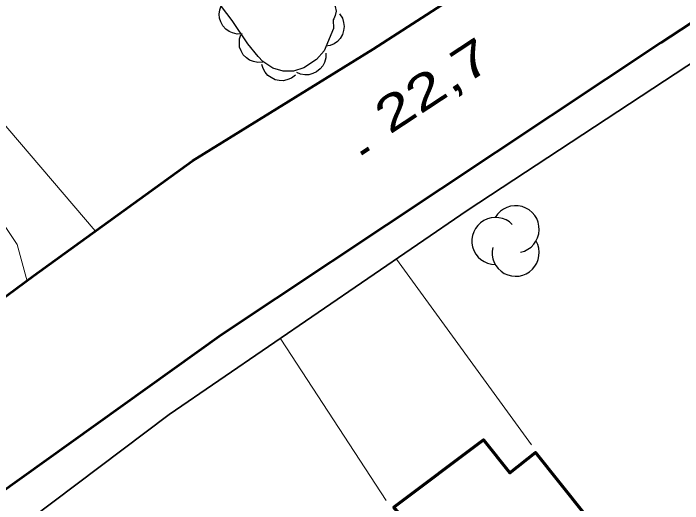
# Model space of a CAD drawing. Extents: x 356765 to 358572, y 5103174 to 5104650.
# Drawn here: x 357410.7 to 357439.35, y 5103860.56 to 5103881.56 of the extents above; entities that cross this region are included whole.
import ezdxf

# ---------------------------------------------------------------- set-up
doc = ezdxf.new("R2010")
doc.units = 0
doc.header["$LTSCALE"] = 0.6
doc.linetypes.add('DOT_DASHED', pattern=[7.7, 5, -1.2, 0.3, -1.2])
for name, color, linetype, lineweight in [('19', 7, 'Continuous', 13), ('21', 7, 'Continuous', 53), ('22', 7, 'Continuous', 35), ('3', 7, 'Continuous', 140), ('31', 7, 'Continuous', 70), ('44', 7, 'Continuous', 25)]:
    doc.layers.add(name, color=color, linetype=linetype, lineweight=lineweight)

msp = doc.modelspace()

# ---------------------------------------------------------------- linework, layer by layer
at = {"layer": '19'}
for p, q in [((357407.69, 5103879.86), (357414.19, 5103872.25)), ((357427.1, 5103871.04), (357432.88, 5103863.08)), ((357422.14, 5103867.61), (357426.65, 5103860.7))]:
    msp.add_line(p, q, dxfattribs=at)
msp.add_lwpolyline([(357411.28, 5103870.09), (357410.85, 5103871.66), (357406.06, 5103878.82)], dxfattribs=at)
at = {"layer": '21'}
for points in [[(357405.87, 5103866.12), (357411.55, 5103870.32), (357418.37, 5103875.25), (357426.1, 5103880.03), (357435.72, 5103886.24), (357444.96, 5103892.47), (357453.86, 5103898.4), (357455.93, 5103900.68), (357456.51, 5103902.67), (357456.67, 5103904.19), (357456.74, 5103905.54), (357456.53, 5103906.97), (357456.28, 5103908.21), (357455.66, 5103909.53), (357453.05, 5103912.5), (357447.62, 5103918.22), (357440.52, 5103925.09), (357433.16, 5103931.82), (357426.68, 5103937.66), (357420.41, 5103943.86), (357414.89, 5103949.01), (357405.38, 5103958.51)], [(357678.36, 5103954.94), (357640.5, 5103946.09), (357619.43, 5103941.41), (357599.16, 5103936.98), (357552.82, 5103926.37), (357536.94, 5103922.93), (357520.26, 5103918.95), (357503.82, 5103914.09), (357486.6, 5103907.55), (357480.97, 5103904.95), (357472.22, 5103900.99), (357457.26, 5103892.04), (357451.72, 5103889.03), (357438.42, 5103880.3), (357419.6, 5103867.79), (357409.99, 5103860.91), (357402.64, 5103855.12), (357395.85, 5103849.3), (357387.1, 5103841.32), (357379.78, 5103834.37), (357370.08, 5103824.18), (357363.77, 5103817.05), (357355.31, 5103807.73), (357353.75, 5103805.99)]]:
    msp.add_lwpolyline(points, dxfattribs=at)
at = {"layer": '22'}
msp.add_lwpolyline([(357647.75, 5103946.51), (357634.21, 5103943.46), (357622.47, 5103940.88), (357609.15, 5103938.01), (357596.04, 5103935), (357584.77, 5103932.34), (357572.98, 5103929.8), (357562.05, 5103927.46), (357547.85, 5103924.19), (357536.87, 5103921.73), (357525.36, 5103918.83), (357514.86, 5103915.9), (357504.84, 5103912.75), (357495.77, 5103909.59), (357486.87, 5103905.97), (357479.16, 5103902.36), (357471.94, 5103898.43), (357462.55, 5103893.01), (357451.44, 5103886.54), (357441.53, 5103880.61), (357430.12, 5103873.12), (357417.36, 5103864.38), (357407.44, 5103856.91)], dxfattribs=at)
at = {"layer": '3'}
msp.add_line((357425.58, 5103875.56), (357425.91, 5103875.78), dxfattribs=at)
at = {"layer": '31'}
msp.add_lwpolyline([(357426.42, 5103857.59), (357428.18, 5103858.95), (357426.99, 5103860.42), (357430.82, 5103863.29), (357431.95, 5103861.88), (357433.05, 5103862.76), (357437.22, 5103857.53), (357430.76, 5103852.26), (357426.42, 5103857.59)], close=True, dxfattribs=at)
at = {"layer": '44', "linetype": 'DOT_DASHED'}
for points in [[(357419.78, 5103890.63), (357419.5, 5103890.55), (357419.02, 5103890.26), (357418.58, 5103889.92), (357418.45, 5103889.71), (357418.51, 5103889.46), (357418.61, 5103889.33), (357419.11, 5103888.83), (357419.77, 5103888.26), (357420.44, 5103887.55), (357420.88, 5103887.01), (357421.76, 5103885.9), (357422.66, 5103884.78), (357423.54, 5103883.67), (357424.06, 5103882.94), (357424.25, 5103882.51), (357424.48, 5103881.86), (357424.51, 5103881.65), (357424.48, 5103881.47), (357424.41, 5103881.32), (357424.39, 5103881.29), (357424.4, 5103880.91), (357424, 5103879.95)], [(357424, 5103879.95), (357423.67, 5103879.59), (357423.13, 5103879.23), (357422.69, 5103879.08), (357422.25, 5103879.08), (357421.81, 5103879.22), (357421.38, 5103879.5), (357421.18, 5103879.71), (357420.74, 5103880.26), (357420.06, 5103881.25), (357419.33, 5103882.22)]]:
    msp.add_lwpolyline(points, dxfattribs=at)
at = {"layer": '44'}
for points in [[(357420.49, 5103880.68), (357420.28, 5103880.67), (357420.08, 5103880.72), (357419.93, 5103880.78), (357419.79, 5103880.89), (357419.67, 5103881.03), (357419.58, 5103881.2), (357419.52, 5103881.35), (357419.51, 5103881.52), (357419.53, 5103881.71), (357419.59, 5103881.88)], [(357424.66, 5103881.54), (357424.78, 5103881.36), (357424.83, 5103881.17), (357424.86, 5103881), (357424.83, 5103880.83), (357424.78, 5103880.65), (357424.68, 5103880.49), (357424.57, 5103880.36), (357424.43, 5103880.26), (357424.26, 5103880.19), (357424.08, 5103880.15)], [(357421.37, 5103879.47), (357421.16, 5103879.45), (357420.97, 5103879.5), (357420.81, 5103879.55), (357420.67, 5103879.66), (357420.54, 5103879.79), (357420.45, 5103879.96), (357420.38, 5103880.11), (357420.37, 5103880.28), (357420.38, 5103880.47), (357420.43, 5103880.64)], [(357424.08, 5103879.86), (357424.07, 5103879.65), (357424.01, 5103879.46), (357423.94, 5103879.31), (357423.83, 5103879.18), (357423.68, 5103879.06), (357423.51, 5103878.98), (357423.35, 5103878.93), (357423.18, 5103878.93), (357422.99, 5103878.96), (357422.83, 5103879.03)], [(357422.77, 5103878.92), (357422.6, 5103878.79), (357422.41, 5103878.71), (357422.25, 5103878.67), (357422.08, 5103878.68), (357421.9, 5103878.72), (357421.73, 5103878.81), (357421.59, 5103878.9), (357421.48, 5103879.04), (357421.39, 5103879.2), (357421.34, 5103879.37)]]:
    msp.add_lwpolyline(points, dxfattribs=at)
for centre, start, end in [((357432.2011, 5103872.317), 282.26917, 149.72626), ((357431.3341, 5103871.8129), 44.11537, 269.80396), ((357432.2011, 5103871.3088), 166.93686, 29.62122)]:
    msp.add_arc(centre, 1.0082, start, end, dxfattribs=at)

# ---------------------------------------------------------------- texts
at = {"layer": '3', "width": 1.4}
msp.add_text('22,7   ', height=1.5, rotation=33.349, dxfattribs=at).set_placement((357426.8, 5103876.35))

doc.saveas('drawing.dxf')
